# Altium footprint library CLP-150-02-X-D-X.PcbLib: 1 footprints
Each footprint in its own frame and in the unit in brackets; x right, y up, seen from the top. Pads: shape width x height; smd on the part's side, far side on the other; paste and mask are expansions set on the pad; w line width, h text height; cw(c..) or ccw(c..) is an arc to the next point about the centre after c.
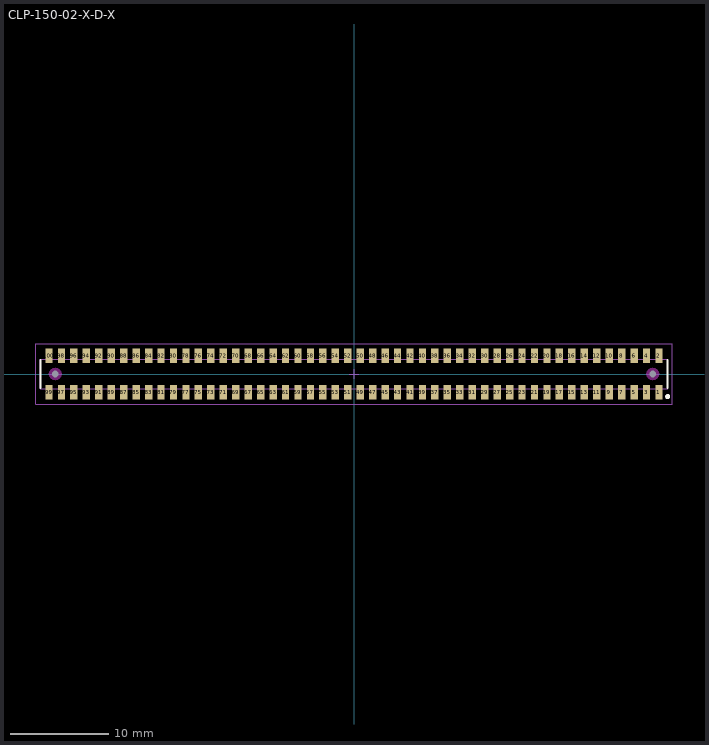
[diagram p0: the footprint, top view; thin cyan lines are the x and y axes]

## CLP-150-02-X-D-X [mm] "1.27mm pitch, 100 pin, socket strip; low profile, horizontal"
height 2.26
pads (102):
  rect 0.75x1.5 smd mask+0: 1(31.115,-1.87) 2(31.115,1.87) 3(29.845,-1.87) 4(29.845,1.87) 5(28.575,-1.87) 6(28.575,1.87) 7(27.305,-1.87) 8(27.305,1.87) 9(26.035,-1.87) 10(26.035,1.87) 11(24.765,-1.87) 12(24.765,1.87) 13(23.495,-1.87) 14(23.495,1.87) 15(22.225,-1.87) 16(22.225,1.87) 17(20.955,-1.87) 18(20.955,1.87) 19(19.685,-1.87) 20(19.685,1.87) 21(18.415,-1.87) 22(18.415,1.87) 23(17.145,-1.87) 24(17.145,1.87) 25(15.875,-1.87) 26(15.875,1.87) 27(14.605,-1.87) 28(14.605,1.87) 29(13.335,-1.87) 30(13.335,1.87) 31(12.065,-1.87) 32(12.065,1.87) 33(10.795,-1.87) 34(10.795,1.87) 35(9.525,-1.87) 36(9.525,1.87) 37(8.255,-1.87) 38(8.255,1.87) 39(6.985,-1.87) 40(6.985,1.87) 41(5.715,-1.87) 42(5.715,1.87) 43(4.445,-1.87) 44(4.445,1.87) 45(3.175,-1.87) 46(3.175,1.87) 47(1.905,-1.87) 48(1.905,1.87) 49(0.635,-1.87) 50(0.635,1.87) 51(-0.635,-1.87) 52(-0.635,1.87) 53(-1.905,-1.87) 54(-1.905,1.87) 55(-3.175,-1.87) 56(-3.175,1.87) 57(-4.445,-1.87) 58(-4.445,1.87) 59(-5.715,-1.87) 60(-5.715,1.87) 61(-6.985,-1.87) 62(-6.985,1.87) 63(-8.255,-1.87) 64(-8.255,1.87) 65(-9.525,-1.87) 66(-9.525,1.87) 67(-10.795,-1.87) 68(-10.795,1.87) 69(-12.065,-1.87) 70(-12.065,1.87) 71(-13.335,-1.87) 72(-13.335,1.87) 73(-14.605,-1.87) 74(-14.605,1.87) 75(-15.875,-1.87) 76(-15.875,1.87) 77(-17.145,-1.87) 78(-17.145,1.87) 79(-18.415,-1.87) 80(-18.415,1.87) 81(-19.685,-1.87) 82(-19.685,1.87) 83(-20.955,-1.87) 84(-20.955,1.87) 85(-22.225,-1.87) 86(-22.225,1.87) 87(-23.495,-1.87) 88(-23.495,1.87) 89(-24.765,-1.87) 90(-24.765,1.87) 91(-26.035,-1.87) 92(-26.035,1.87) 93(-27.305,-1.87) 94(-27.305,1.87) 95(-28.575,-1.87) 96(-28.575,1.87) 97(-29.845,-1.87) 98(-29.845,1.87) 99(-31.115,-1.87) 100(-31.115,1.87)
  round 0.5 hole 0.7 unplated mask+0: 101(-30.48,0) 102(30.48,0)
Top Overlay:
  circle w0.25: c32,-2.3 r0.125
  lines w0.2: -32,-1.45 -32,1.45 ; 32,-1.45 32,1.45
Keep-Out Layer:
  pour cut-out: -29.833,0 -29.882,0.248 -30.022,0.458 -30.232,0.598 -30.48,0.647 -30.728,0.598 -30.938,0.458 -31.078,0.248 -31.127,0 -31.078,-0.248 -30.938,-0.458 -30.728,-0.598 -30.48,-0.647 -30.232,-0.598 -30.022,-0.458 -29.882,-0.248
  pour cut-out: 31.127,0 31.078,0.248 30.938,0.458 30.728,0.598 30.48,0.647 30.232,0.598 30.022,0.458 29.882,0.248 29.833,0 29.882,-0.248 30.022,-0.458 30.232,-0.598 30.48,-0.647 30.728,-0.598 30.938,-0.458 31.078,-0.248
Mechanical 12:
  lines w0.001: -32,-1.5 32,-1.5 32,1.5 -32,1.5 -32,-1.5
Mechanical 13:
  lines w0.1: -32,-1.5 32,-1.5 32,1.5 -32,1.5 -32,-1.5
  text ".Designator" at 0.254,0.254 h1.52
Mechanical 15:
  lines w0.05: -0.5,0 0.5,0 ; 0,-0.5 0,0.5 ; -32.461,-3.099 32.461,-3.099 32.461,3.099 -32.461,3.099 -32.461,-3.099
